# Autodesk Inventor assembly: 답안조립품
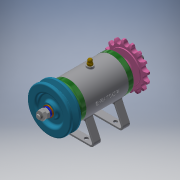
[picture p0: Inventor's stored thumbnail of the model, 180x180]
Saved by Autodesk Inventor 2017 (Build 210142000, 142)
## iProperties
Part Number: 답안조립품
Material: 일반
Document SubType Name: Assembly
Designer: Administrator
Author: Administrator
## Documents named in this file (16)
- C:\Users\Administrator\Desktop\711206V1034\답안조립품.iam
- C:\Users\Administrator\Desktop\711206V1034\본체.ipt
- C:\Users\Administrator\Desktop\711206V1034\V벨트풀리.ipt
- C:\Users\Administrator\Desktop\711206V1034\축.ipt
- C:\Users\Administrator\Desktop\711206V1034\베어링 6002.ipt
- C:\Users\Administrator\Desktop\711206V1034\키 3 x 3.ipt
- C:\Users\Administrator\Desktop\711206V1034\오일 실 15 x 25 x 7.ipt
- C:\Users\Administrator\Desktop\711206V1034\커버.ipt
- C:\Users\Administrator\Desktop\711206V1034\볼트 M4 x 12.ipt
- C:\Users\Administrator\Desktop\711206V1034\와셔 8 x 17.ipt
- C:\Users\Administrator\Desktop\711206V1034\너트 M8.ipt
- C:\Users\Administrator\Desktop\711206V1034\스프링와셔 8.ipt
- C:\Users\Administrator\Desktop\711206V1034\스프로킷.ipt
- C:\Users\Administrator\Desktop\711206V1034\니플 M6 x 0.75.ipt
- C:\Users\Administrator\Desktop\711206V1034\와셔 6 x 11.5.ipt
- C:\Users\Administrator\Desktop\711206V1034\볼트 M6 x 8.ipt
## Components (11 placed, 3 different names)
1. V벨트풀리:1
2. KS B 2023 6002 - 15 x 32 x 9:1
3. KS B 2023 6002 - 15 x 32 x 9:2
4. ISO 4762 M4 x 12:1
5. ISO 4762 M4 x 12:3
6. ISO 4762 M4 x 12:4
7. ISO 4762 M4 x 12:5
8. ISO 4762 M4 x 12:2
9. ISO 4762 M4 x 12:6
10. ISO 4762 M4 x 12:7
11. ISO 4762 M4 x 12:8
